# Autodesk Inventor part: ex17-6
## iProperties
Created: 2006-04
Part Number: ex17-6
Project: EVERGREEN VALLEY COLLEGE
Description: EXT CLIP, AXIAL ROTOR CLIP
Document SubType Name: Modeling
Designer: E. MOSS
Authority: MS. TEACHER
Author: E. MOSS
Revision Number: A
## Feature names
1. Extrusion1
